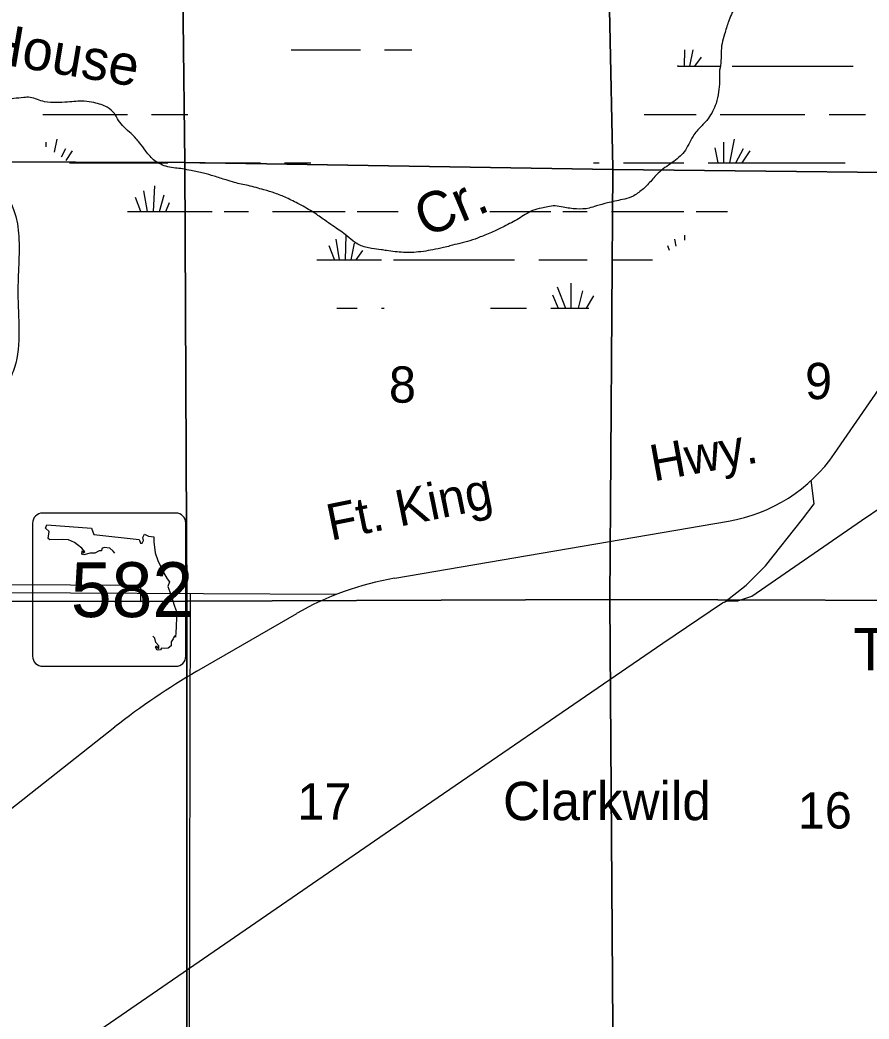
# Model space of a CAD drawing. Extents: x 380424 to 701066, y 1117407 to 1412949.
# Drawn here: x 545894 to 556420, y 1347425 to 1359814 of the extents above; entities that cross this region are included whole.
import ezdxf

# ---------------------------------------------------------------- set-up
doc = ezdxf.new("R2010")
doc.units = 0
for name, color, linetype in [('Communities and Subdivisions Names without Post Office', 7, 'Continuous'), ('Communities Names with Post Office', 7, 'Continuous'), ('Local Roads Paved', 7, 'Continuous'), ('Narrow River Creek and Branch and Slough', 7, 'Continuous'), ('Narrow River Creek and Branch and Slough Text', 7, 'Continuous'), ('Roadshilelds State Highways', 7, 'Continuous'), ('Section Lines', 7, 'Continuous'), ('Section Numbers', 7, 'Continuous'), ('State Route Divided Highway Outline and Fill', 7, 'Continuous'), ('State Routes Highway Center Lines', 7, 'Continuous'), ('Swamps', 7, 'Continuous'), ('US Highways Related Text', 7, 'Continuous'), ('US Routes Highway Center Lines', 7, 'Continuous'), ('Wide Rivers and Canals', 7, 'Continuous')]:
    doc.layers.add(name, color=color, linetype=linetype)

msp = doc.modelspace()

# ---------------------------------------------------------------- linework, layer by layer
at = {"layer": 'Local Roads Paved'}
msp.add_line((548003, 1352699), (547986, 1344736), dxfattribs=at)
for points in [[(554626, 1352594), (554897, 1352804), (555138, 1353044), (555597, 1353624), (555739, 1353815), (555704, 1354106)], [(544188, 1345446), (544892, 1345923), (550487, 1349771), (553862, 1352084), (554602, 1352584), (554662, 1352609), (554792, 1352609), (554967, 1352669), (556327, 1353605), (556597, 1353790), (556747, 1353865), (556946, 1353910), (561568, 1353911), (562533, 1353912)]]:
    msp.add_lwpolyline(points, dxfattribs=at)
at = {"layer": 'Narrow River Creek and Branch and Slough'}
msp.add_spline([(554921, 1360827), (554872, 1360485), (554845, 1360316), (554829, 1360173), (554755, 1359973), (554676, 1359793), (554629, 1359640), (554597, 1359524), (554587, 1359403), (554581, 1359281), (554565, 1359160), (554565, 1359049), (554555, 1358922), (554523, 1358780), (554481, 1358680), (554428, 1358595), (554338, 1358495), (554238, 1358373), (554127, 1358178), (553980, 1358046), (553805, 1357914), (553700, 1357798), (553594, 1357698), (553473, 1357619), (553362, 1357587), (553177, 1357545), (553040, 1357508), (552950, 1357481), (552792, 1357471), (552628, 1357492), (552528, 1357508), (552438, 1357497), (552359, 1357481), (552248, 1357450), (552158, 1357402), (552074, 1357349), (551895, 1357254), (551757, 1357186), (551599, 1357123), (551472, 1357075), (551346, 1357043), (551224, 1357012), (551145, 1356991), (551013, 1356964), (550776, 1356932), (550649, 1356932), (550438, 1356954), (550374, 1356964), (550253, 1356980), (550105, 1357022), (550021, 1357075), (549926, 1357154), (549773, 1357260), (549667, 1357334), (549540, 1357423), (549356, 1357529), (549197, 1357608), (549055, 1357666), (548918, 1357708), (548722, 1357761), (548553, 1357798), (548448, 1357830), (548300, 1357877), (548168, 1357914), (548015, 1357946), (547909, 1357967), (547820, 1357978), (547725, 1357993), (547640, 1358025), (547566, 1358067), (547455, 1358189), (547376, 1358289), (547334, 1358342), (547165, 1358505), (547102, 1358590), (547065, 1358653), (546975, 1358732), (546901, 1358764), (546811, 1358790), (546690, 1358806), (546484, 1358796), (546342, 1358790), (546199, 1358801), (546109, 1358827), (546020, 1358854), (545940, 1358852), (545818, 1358840), (545648, 1358809), (545570, 1358785), (545472, 1358743), (545387, 1358706), (545315, 1358688), (545254, 1358670), (545157, 1358639), (545004, 1358566)], degree=3, dxfattribs=at)
at = {"layer": 'Roadshilelds State Highways'}
for p, q in [((547825, 1353699), (546175, 1353699)), ((546050, 1353574), (546050, 1351924)), ((547950, 1351924), (547950, 1353574)), ((546175, 1351799), (547825, 1351799))]:
    msp.add_line(p, q, dxfattribs=at)
for points in [[(547070, 1353200), (547050, 1353225), (547007, 1353262), (546938, 1353272), (546908, 1353258), (546905, 1353229), (546875, 1353232), (546823, 1353202), (546763, 1353202), (546687, 1353182), (546661, 1353189), (546664, 1353232), (546681, 1353202), (546697, 1353219), (546661, 1353262), (546605, 1353305), (546569, 1353334), (546496, 1353367), (546420, 1353370), (546265, 1353367), (546242, 1353384), (546256, 1353469), (546209, 1353512), (546226, 1353552)], [(546226, 1353552), (546780, 1353512), (546809, 1353433), (547373, 1353370), (547386, 1353324), (547409, 1353324), (547426, 1353357), (547416, 1353397), (547436, 1353436), (547485, 1353413), (547551, 1353403), (547551, 1353341), (547571, 1353206), (547604, 1353110), (547673, 1352961), (547719, 1352882), (547746, 1352846), (547726, 1352790), (547752, 1352721), (547785, 1352625), (547808, 1352546), (547835, 1352477), (547835, 1352414), (547828, 1352289), (547825, 1352216), (547821, 1352160), (547808, 1352177), (547792, 1352140), (547769, 1352101), (547769, 1352054), (547729, 1352025), (547686, 1352018), (547650, 1352025), (547637, 1352005), (547594, 1351998), (547574, 1352035), (547584, 1352051), (547597, 1352028), (547614, 1352021), (547614, 1352051), (547577, 1352094), (547564, 1352147), (547542, 1352171)]]:
    msp.add_lwpolyline(points, dxfattribs=at)
for centre, start, end in [((546175, 1353574), 89.9997, 179.9997), ((547825, 1353574), 359.9997, 89.9997), ((546175, 1351924), 179.9997, 269.9997), ((547825, 1351924), 269.9997, 359.9997)]:
    msp.add_arc(centre, 125, start, end, dxfattribs=at)
at = {"layer": 'Section Lines'}
for points in [[(547875, 1363334), (547939, 1358045), (547934, 1358045), (542526, 1358063), (542475, 1363347), (542478, 1363354)], [(553132, 1363292), (553244, 1357982), (553243, 1357961), (547939, 1358045), (547875, 1363334)], [(558542, 1363220), (558555, 1357902), (553243, 1357961), (553244, 1357982), (553132, 1363292), (553159, 1363292)], [(547939, 1358045), (547939, 1358037), (547961, 1352608), (542508, 1352602), (542500, 1352603), (542526, 1358063), (547934, 1358045)], [(553243, 1357961), (553205, 1352626), (547973, 1352608), (547961, 1352608), (547939, 1358037), (547939, 1358045)], [(558555, 1357902), (558556, 1357891), (558547, 1352610), (553210, 1352626), (553205, 1352626), (553243, 1357961)], [(547961, 1352608), (547961, 1352601), (547963, 1347288), (542507, 1347325), (542500, 1352603), (542508, 1352602)], [(553205, 1352626), (553205, 1352614), (553243, 1347318), (547963, 1347288), (547961, 1352601), (547961, 1352608), (547973, 1352608)], [(558547, 1352610), (558547, 1352601), (558536, 1347295), (558524, 1347296), (553243, 1347318), (553205, 1352614), (553205, 1352626), (553210, 1352626)]]:
    msp.add_lwpolyline(points, close=True, dxfattribs=at)
at = {"layer": 'State Route Divided Highway Outline and Fill'}
msp.add_lwpolyline([(539072, 1352643), (546518, 1352606), (547390, 1352602), (547390, 1352802), (546519, 1352806), (539073, 1352843), (531019, 1352884), (508998, 1352993), (508208, 1352997), (508205, 1352797), (508997, 1352793), (531018, 1352684)], close=True, dxfattribs=at)
at = {"layer": 'State Routes Highway Center Lines'}
msp.add_lwpolyline([(549817, 1352690), (546518, 1352706), (539072, 1352743), (531019, 1352784), (508998, 1352893), (508106, 1352898)], dxfattribs=at)
at = {"layer": 'Swamps'}
for p, q in [((554198, 1359241), (554241, 1359446)), ((554261, 1359240), (554344, 1359354)), ((554725, 1359241), (556225, 1359241)), ((546175, 1358641), (547225, 1358641)), ((547525, 1358641), (547975, 1358641)), ((553825, 1358641), (554275, 1358641)), ((554575, 1358641), (555625, 1358641)), ((555925, 1358641), (556375, 1358641)), ((554616, 1358299), (554616, 1358041)), ((554749, 1358336), (554690, 1358041)), ((554507, 1358227), (554544, 1358041)), ((554858, 1358215), (554764, 1358040)), ((554942, 1358191), (554843, 1358042)), ((548125, 1358041), (548875, 1358041)), ((553375, 1358041), (553825, 1358041)), ((553825, 1358041), (554125, 1358041)), ((554425, 1358041), (556125, 1358041)), ((547476, 1357441), (547429, 1357695)), ((547547, 1357441), (547564, 1357757)), ((547623, 1357441), (547681, 1357645)), ((547390, 1357441), (547325, 1357613)), ((547700, 1357441), (547749, 1357550)), ((547225, 1357441), (548275, 1357441)), ((548425, 1357441), (548725, 1357441)), ((549025, 1357441), (549625, 1357441)), ((549625, 1357441), (549925, 1357441)), ((550075, 1357441), (550583, 1357441)), ((551719, 1357441), (552475, 1357441)), ((552625, 1357441), (552925, 1357441)), ((553225, 1357441), (553825, 1357441)), ((553825, 1357441), (554125, 1357441)), ((549853, 1356841), (549814, 1357094)), ((549931, 1356841), (549937, 1357145)), ((549998, 1356841), (550041, 1357046)), ((549791, 1356842), (549725, 1357015)), ((550060, 1356840), (550144, 1356954)), ((549625, 1356841), (550375, 1356841)), ((550525, 1356841), (552025, 1356841)), ((552325, 1356841), (552925, 1356841)), ((552724, 1356552), (552724, 1356241)), ((552494, 1356407), (552565, 1356241)), ((552555, 1356503), (552658, 1356241)), ((552869, 1356455), (552815, 1356241)), ((551725, 1356241), (552175, 1356241))]:
    msp.add_line(p, q, dxfattribs=at)
for points in [[(549255, 1359442), (550114, 1359442)], [(550414, 1359442), (550750, 1359442)], [(554131, 1359241), (554135, 1359446)], [(554047, 1359241), (554575, 1359241)], [(554053, 1359241), (554051, 1359251)], [(553632, 1358641), (553825, 1358641)], [(546216, 1358299), (546216, 1358241)], [(546349, 1358336), (546316, 1358173)], [(546458, 1358215), (546403, 1358113)], [(546542, 1358191), (546463, 1358072)], [(546509, 1358041), (547725, 1358041)], [(549175, 1358041), (549501, 1358041)], [(553004, 1358041), (553075, 1358041)], [(554275, 1357441), (554665, 1357441)], [(554027, 1357010), (554014, 1357094)], [(554136, 1357084), (554137, 1357145)], [(553947, 1356957), (553925, 1357015)], [(549572, 1356841), (549625, 1356841)], [(553225, 1356841), (553737, 1356841)], [(553002, 1356395), (552912, 1356241)], [(549821, 1356241), (550075, 1356241)], [(550375, 1356241), (550410, 1356241)], [(552475, 1356241), (552948, 1356241)]]:
    msp.add_lwpolyline(points, dxfattribs=at)
at = {"layer": 'US Routes Highway Center Lines'}
for p, q in [((555992, 1354438), (558334, 1357836)), ((550539, 1352891), (554678, 1353599)), ((545025, 1349436), (547069, 1351047))]:
    msp.add_line(p, q, dxfattribs=at)
msp.add_lwpolyline([(548087, 1351737), (548087, 1351737), (549324, 1352452)], dxfattribs=at)
for centre, radius, start, end in [((554340, 1355577), 2007, 279.7014, 325.4243), ((551155, 1349284), 3660, 99.7018, 120.0332), ((552387, 1344299), 8591, 120.0329, 128.2446)]:
    msp.add_arc(centre, radius, start, end, dxfattribs=at)
at = {"layer": 'Wide Rivers and Canals'}
msp.add_spline([(544639, 1359244), (544692, 1359061), (544864, 1358761), (544975, 1358603), (545038, 1358523), (545861, 1357288), (545879, 1357130), (545867, 1356432), (545825, 1355503), (545746, 1355308), (545619, 1355047), (545046, 1354073), (544976, 1353865), (544996, 1353768), (544985, 1353613), (545020, 1352919)], degree=3, dxfattribs=at)

# ---------------------------------------------------------------- texts
at = {"layer": 'Communities and Subdivisions Names without Post Office'}
msp.add_text('Clarkwild', height=475, rotation=0.0004, dxfattribs=at).set_placement((551882, 1349891))
at = {"layer": 'Communities Names with Post Office'}
msp.add_text('THONOTOSASSA', height=525, rotation=0.0003, dxfattribs=at).set_placement((556227, 1351747))
at = {"layer": 'Narrow River Creek and Branch and Slough Text'}
for s, rotation, p in [('House', 350.538, (545421, 1359303)), ('Cr.', 22.813, (550920, 1357113))]:
    msp.add_text(s, height=500, rotation=rotation, dxfattribs=at).set_placement(p)
at = {"layer": 'Roadshilelds State Highways'}
msp.add_text('582', height=680, rotation=359.9997, dxfattribs=at).set_placement((546524, 1352409))
at = {"layer": 'Section Numbers'}
for s, p in [('9', (555627, 1355112)), ('8', (550468, 1355068)), ('17', (549333, 1349898)), ('16', (555537, 1349787))]:
    msp.add_text(s, height=450, dxfattribs=at).set_placement(p)
at = {"layer": 'US Highways Related Text'}
for s, rotation, p in [('Hwy.', 10.284, (553749, 1354091)), ('Ft. King', 11.5136, (549747, 1353356))]:
    msp.add_text(s, height=450, rotation=rotation, dxfattribs=at).set_placement(p)

doc.saveas('drawing.dxf')
